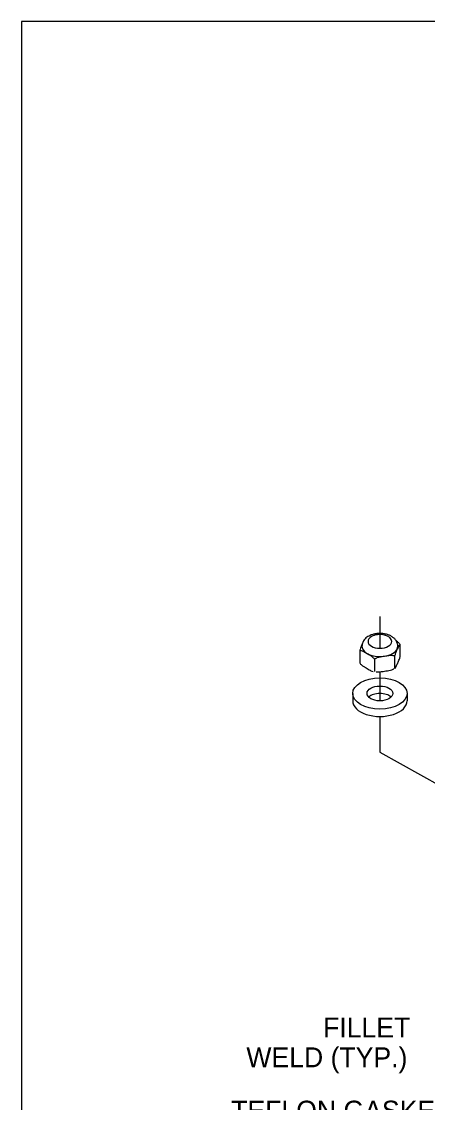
# Model space of a CAD drawing. Extents: x 99862 to 103151, y 99997 to 117076.
# Drawn here: x 99862 to 100188, y 116205 to 117076 of the extents above; entities that cross this region are included whole.
import ezdxf

# ---------------------------------------------------------------- set-up
doc = ezdxf.new("R2010")
doc.units = 0
for name, color, linetype in [('Level 1', 7, 'Continuous'), ('Level 12', 7, 'Continuous'), ('Level 15', 7, 'Continuous'), ('Level 20', 7, 'Continuous')]:
    doc.layers.add(name, color=color, linetype=linetype)

msp = doc.modelspace()

# ---------------------------------------------------------------- linework, layer by layer
at = {"layer": 'Level 1'}
msp.add_lwpolyline([(99862, 114999.5), (103151, 114999.5), (103151, 117075.5), (99862, 117075.5)], close=True, dxfattribs=at)
at = {"layer": 'Level 12'}
for p, q in [((100166.45, 116564.1), (100166.45, 116574.01)), ((100133.95, 116568.98), (100133.95, 116559.07)), ((100162.09, 116564.63), (100162.09, 116554.72)), ((100145.84, 116562.11), (100145.84, 116552.2)), ((100128.34, 116534.52), (100128.34, 116528.57)), ((100172.05, 116534.52), (100172.05, 116528.57))]:
    msp.add_line(p, q, dxfattribs=at)
for centre, major_axis, start_param, end_param in [((100150.2, 116576.45), (9.54, 0), 6.283185, 8.63938), ((100150.2, 116572.49), (-14.39, 0), 0, 3.141593), ((100150.2, 116576.45), (9.54, 0), 2.356194, 3.141593), ((100150.2, 116576.45), (9.54, 0), 3.141593, 6.283185), ((100150.2, 116528.57), (-21.85, 0), 0, 3.141593), ((100150.2, 116528.57), (-10.32, 0), 3.664192, 5.760586)]:
    msp.add_ellipse(centre, major_axis=major_axis, ratio=0.57735, start_param=start_param, end_param=end_param, dxfattribs=at)
for major_axis in [(-21.85, 0), (-10.32, 0)]:
    msp.add_ellipse((100150.2, 116534.52), major_axis=major_axis, ratio=0.57735, dxfattribs=at)
for points in [[(100164.59, 116572.49), (100164.59, 116574.01), (100164.04, 116575.77), (100162.36, 116578.36), (100160.96, 116579.64), (100158.27, 116581.25), (100156.54, 116581.92), (100153.09, 116582.75), (100150.71, 116582.94), (100146.72, 116582.66), (100144.42, 116582.14), (100142.14, 116581.18), (100141.52, 116580.87), (100139.68, 116579.81), (100138.31, 116578.64), (100136.93, 116576.71), (100136.45, 116575.77), (100135.95, 116574.19), (100135.8, 116573.27), (100135.8, 116572.49)], [(100136.07, 116574.54), (100135.49, 116573.29), (100134.8, 116571.87), (100134.15, 116569.78), (100134.04, 116569.38), (100133.95, 116568.98)], [(100166.45, 116574.01), (100166.35, 116574), (100166.24, 116573.91), (100165.58, 116573.21), (100164.86, 116571.59), (100164.27, 116570.3), (100163.67, 116569.02), (100162.96, 116567.57), (100162.3, 116565.42), (100162.19, 116565.03), (100162.09, 116564.63)], [(100166.45, 116574.01), (100166.19, 116574.35), (100165.88, 116574.69), (100164.95, 116575.6), (100164.21, 116576.15), (100163.46, 116576.66)], [(100145.84, 116562.11), (100145.58, 116562.46), (100145.28, 116562.79), (100143.47, 116564.56), (100141.52, 116565.6), (100139.9, 116566.53), (100138.27, 116567.47), (100136.32, 116568.68), (100134.51, 116569.01), (100134.21, 116569.03), (100133.95, 116568.98)], [(100162.09, 116564.63), (100161.74, 116564.77), (100161.32, 116564.86), (100158.85, 116565.2), (100156.19, 116564.7), (100153.97, 116564.36), (100151.75, 116564.01), (100149.09, 116563.69), (100146.61, 116562.58), (100146.2, 116562.36), (100145.84, 116562.11)], [(100162.22, 116554.76), (100162.28, 116554.8), (100162.34, 116554.86), (100162.96, 116555.52), (100163.67, 116557.14), (100164.27, 116558.42), (100164.86, 116559.7), (100165.58, 116561.15), (100166.24, 116563.3), (100166.35, 116563.7), (100166.45, 116564.1)], [(100133.95, 116559.07), (100134.21, 116558.73), (100134.51, 116558.39), (100136.32, 116556.63), (100138.27, 116555.59), (100139.9, 116554.65), (100141.49, 116553.73), (100143.39, 116552.55), (100144.91, 116552.25)], [(100147.18, 116551.9), (100149.25, 116551.66), (100151.82, 116552.14), (100153.97, 116552.47), (100156.19, 116552.82), (100158.85, 116553.14), (100161.12, 116554.16), (100161.31, 116554.25), (100161.49, 116554.35)]]:
    msp.add_open_spline(points, degree=3, dxfattribs=at)
at = {"layer": 'Level 15'}
for p, q in [((100150.2, 116596.45), (100150.2, 116570.95)), ((100150.2, 116564.18), (100150.2, 116563.73)), ((100150.2, 116551.94), (100150.2, 116528.56)), ((100150.2, 116515.95), (100150.2, 116487.22))]:
    msp.add_line(p, q, dxfattribs=at)
msp.add_lwpolyline([(100150.2, 116487.22), (100330.1, 116386.76)], dxfattribs=at)

# ---------------------------------------------------------------- texts
at = {"layer": 'Level 20'}
for s, p in [('FILLET', (100104.51, 116257.53)), ('WELD (TYP.)', (100042.79, 116233.53)), ('TEFLON GASKET', (100030.6, 116190.6))]:
    msp.add_text(s, height=16, dxfattribs=at).set_placement(p)

doc.saveas('drawing.dxf')
